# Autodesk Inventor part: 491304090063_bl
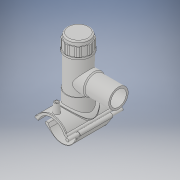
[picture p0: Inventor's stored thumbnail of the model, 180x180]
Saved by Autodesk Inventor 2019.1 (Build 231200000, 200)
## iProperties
Created: 2017-07
Part Number: 491304090063_bl
Material: Generic
Description: PLASSON TAPPING TEE SADDLE 90mm x 63mm
Document SubType Name: Modeling
Designer: KIM
Mass: 1712.7 g
Surface Area: 2671.49 cm^2
Volume: 1712.7 cm^3
Density: 1 g/cm^3
Appearance: Default
Author: KIM
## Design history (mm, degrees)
derived "491304.ipt"
feature "Solid1::491304.ipt" dims "ScaleForDerivedMember" = 10
feature "Solid2::491304.ipt" dims "ScaleForDerivedMember" = 10
feature "Solid4::491304.ipt" dims "ScaleForDerivedMember" = 10
feature "Solid5::491304.ipt" dims "ScaleForDerivedMember" = 10
tag "TaggingFeature1"
body "Solid1"
body "Solid2"
other parameters: "d1" = 101.118 [user parameter], "d2" = 222.4 [user parameter], "d3" = 22.5 [user parameter], "d4" = 176 [user parameter], "d5" = 0 [user parameter], "d6" = 0.1 [user parameter], "d8" = 0 [user parameter], "d40" = 54 [user parameter], "d41" = 97.65 [user parameter], "d43" = 0 [user parameter], "d45" = 0 [user parameter], "d47" = 156.159 [user parameter], "d79" = 15 [user parameter], "d80" = 70.4 [user parameter], "d82" = 5 deg [user parameter], "d84" = 4 [user parameter], "d85" = 14 [user parameter], "d86" = 0 [user parameter], "d87" = 3 [user parameter], "d88" = 0 [user parameter], "d97" = 3.52 [user parameter], "d98" = 0 [user parameter], "d102" = 0.9 [user parameter], "d120" = 140 deg [user parameter], "d123" = 606.708 [user parameter], "d126" = 0 [user parameter], "d153" = 176 [user parameter], "d154" = 0 [user parameter], "d159" = 2.2236 [user parameter], "d162" = 105.6 [user parameter], "d163" = 0 [user parameter], "d164" = 45 [user parameter], "d169" = 4.0905 [user parameter], "d172" = 0 [user parameter], "d173" = 1 [user parameter], "d175" = 45 [user parameter], "d176" = 20 deg [user parameter], "d177" = 6.3 [user parameter], "d180" = 0 [user parameter], "d184" = 5.04 [user parameter], "d187" = 49.5 [user parameter], "d188" = 15 [user parameter], "d189" = 6.3 [user parameter], "d190" = 0 [user parameter], "d191" = 67.5 [user parameter], "d195" = 90 deg [user parameter], "d197" = 0 [user parameter], "d199" = 0 [user parameter], "d200" = 6.3 [user parameter], "d202" = 0 [user parameter], "d203" = 195 [user parameter], "d206" = 75.6 [user parameter], "d207" = 146.25 [user parameter], "d208" = 152.1 [user parameter], "d209" = 181.35 [user parameter], "d210" = 76.86 [user parameter], "d212" = 72.45 [user parameter], "d213" = 39.15 [user parameter], "d216" = 0 [user parameter], "d217" = 9 [user parameter], "d218" = 4.5 [user parameter], "d219" = 0.9 [user parameter], "d224" = 0 [user parameter], "d259" = 50.4 [user parameter], "d260" = 63 [user parameter], "d263" = 139 [user parameter], "d265" = 0 [user parameter], "d267" = 13.00006 [user parameter], "d268" = 2.60001 [user parameter], "d269" = 2.60001 [user parameter], "d271" = 2.60001 [user parameter], "d273" = 0 [user parameter], "d274" = 23.56194 [user parameter], "d275" = 72 [user parameter], "d277" = 36 [user parameter], "d278" = 144 [user parameter], "d280" = 0 [user parameter], "d283" = 0 [user parameter], "d285" = 0 [user parameter], "d290" = 9 [user parameter], "d293" = 49.5 [user parameter], "d294" = 46.35 [user parameter], "d296" = 13.5 [user parameter], "d299" = 75 [user parameter], "d300" = 3 [user parameter], "d301" = 5 [user parameter], "d303" = 81.9 [user parameter], "d304" = 69.3 [user parameter], "d305" = 45 deg [user parameter], "d306" = 50.4 [user parameter], "d307" = 56.25 [user parameter], "d308" = 54 [user parameter], "d310" = 1 [user parameter], "B" = 139 [user parameter], "L" = 176 [user parameter], "d_t" = 6 [user parameter], "H2" = 195 [user parameter], "H1" = 75 [user parameter], "d_1" = 63 [user parameter]
